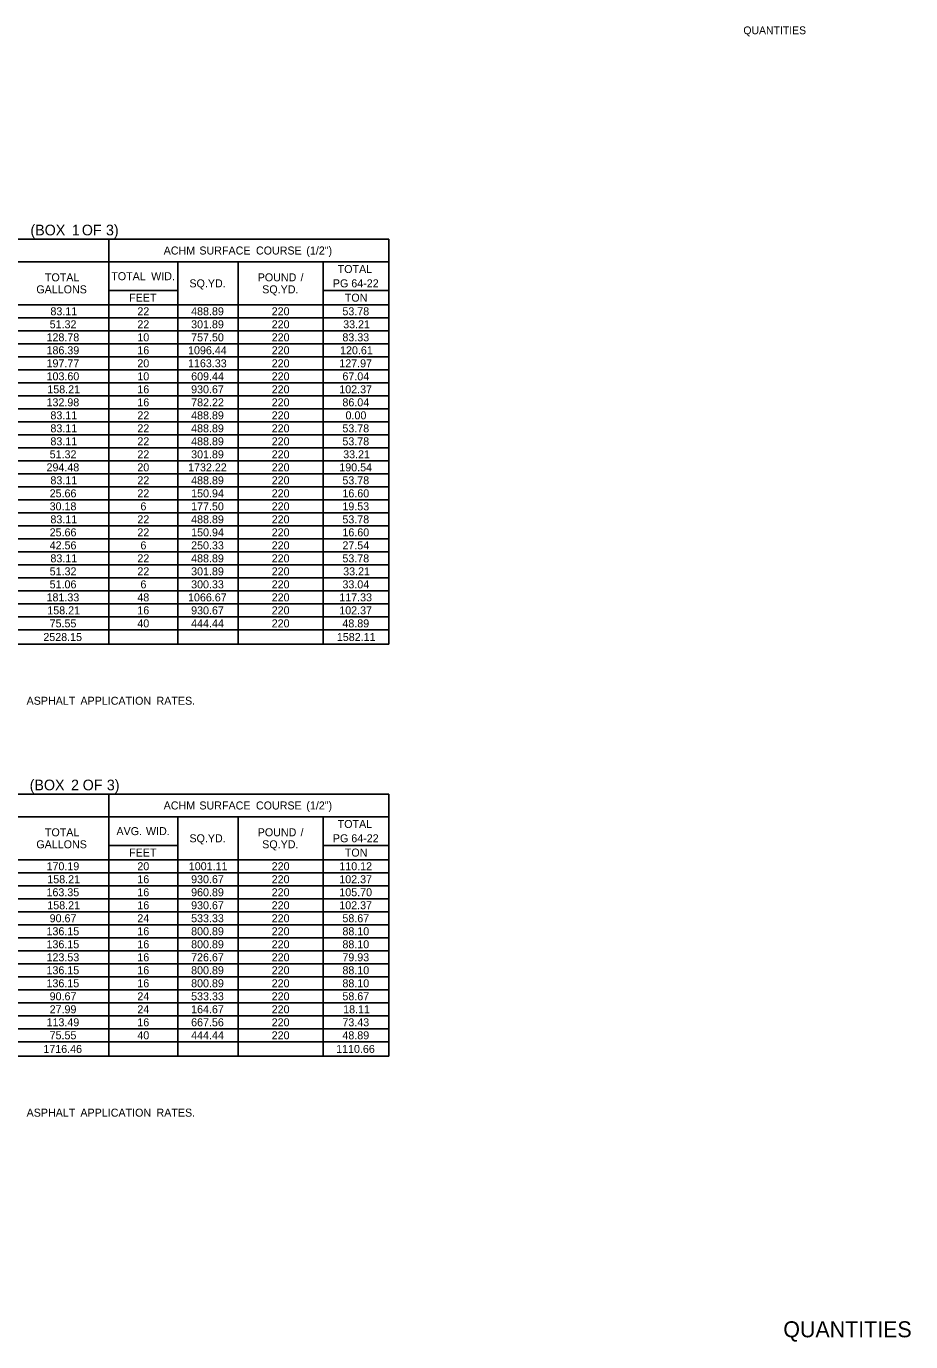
# Model space of a CAD drawing. Extents: x 544250 to 1930787, y -1948365 to 596640.
# Drawn here: x 552725 to 553389, y -1947044 to -1946058 of the extents above; entities that cross this region are included whole.
import ezdxf

# ---------------------------------------------------------------- set-up
doc = ezdxf.new("R2010")
doc.units = 0
for name, color, linetype in [('Default', 7, 'Continuous'), ('R_Border', 7, 'Continuous'), ('R_Border Prem', 7, 'Continuous')]:
    doc.layers.add(name, color=color, linetype=linetype)

msp = doc.modelspace()

# ---------------------------------------------------------------- linework, layer by layer
at = {"layer": 'Default'}
for p, q in [((552201.23, -1946217.53), (552997.32, -1946217.53)), ((552787.2, -1946521.24), (552787.2, -1946217.53)), ((552997.32, -1946521.24), (552997.32, -1946217.53)), ((552612.68, -1946234.59), (552997.32, -1946234.59)), ((552838.88, -1946234.59), (552884.22, -1946234.59)), ((552838.88, -1946521.24), (552838.88, -1946234.59)), ((552884.22, -1946521.24), (552884.22, -1946234.59)), ((552948.08, -1946521.24), (552948.08, -1946234.59)), ((552787.2, -1946256.04), (552838.88, -1946256.04)), ((552787.2, -1946266.77), (552787.2, -1946256.04)), ((552838.88, -1946266.77), (552838.88, -1946256.04)), ((552948.08, -1946256.04), (552997.32, -1946256.04)), ((552413.78, -1946266.77), (552997.32, -1946266.77)), ((552672.15, -1946266.77), (552838.88, -1946266.77)), ((552838.88, -1946266.77), (552997.32, -1946266.77)), ((552413.78, -1946276.52), (552997.32, -1946276.52)), ((552201.23, -1946286.27), (552997.32, -1946286.27)), ((552201.23, -1946286.27), (552997.32, -1946286.27)), ((552201.23, -1946296.02), (552997.32, -1946296.02)), ((552201.23, -1946296.02), (552997.32, -1946296.02)), ((552201.23, -1946305.77), (552997.32, -1946305.77)), ((552201.23, -1946305.77), (552997.32, -1946305.77)), ((552201.23, -1946315.52), (552997.32, -1946315.52)), ((552201.23, -1946315.52), (552997.32, -1946315.52)), ((552201.23, -1946325.27), (552997.32, -1946325.27)), ((552201.23, -1946325.27), (552997.32, -1946325.27)), ((552201.23, -1946335.02), (552997.32, -1946335.02)), ((552201.23, -1946335.02), (552997.32, -1946335.02)), ((552201.23, -1946344.77), (552997.32, -1946344.77)), ((552201.23, -1946344.77), (552997.32, -1946344.77)), ((552201.23, -1946354.52), (552997.32, -1946354.52)), ((552201.23, -1946364.27), (552997.32, -1946364.27)), ((552672.15, -1946364.27), (552997.32, -1946364.27)), ((552672.15, -1946374.02), (552997.32, -1946374.02)), ((552201.23, -1946383.77), (552997.32, -1946383.77)), ((552201.23, -1946383.77), (552997.32, -1946383.77)), ((552201.23, -1946393.52), (552997.32, -1946393.52)), ((552201.23, -1946393.52), (552997.32, -1946393.52)), ((552413.78, -1946403.27), (552997.32, -1946403.27)), ((552413.78, -1946413.02), (552997.32, -1946413.02)), ((552201.23, -1946422.77), (552997.32, -1946422.77)), ((552201.23, -1946422.77), (552997.32, -1946422.77)), ((552413.78, -1946432.52), (552997.32, -1946432.52)), ((552413.78, -1946442.27), (552997.32, -1946442.27)), ((552201.23, -1946452.02), (552997.32, -1946452.02)), ((552201.23, -1946452.02), (552997.32, -1946452.02)), ((552413.78, -1946461.77), (552997.32, -1946461.77)), ((552413.78, -1946471.52), (552997.32, -1946471.52)), ((552201.23, -1946481.27), (552997.32, -1946481.27)), ((552413.78, -1946491.02), (552997.32, -1946491.02)), ((552672.15, -1946491.02), (552997.32, -1946491.02)), ((552201.23, -1946500.77), (552997.32, -1946500.77)), ((552413.78, -1946500.77), (552997.32, -1946500.77)), ((552201.23, -1946510.52), (552997.32, -1946510.52)), ((552201.23, -1946521.24), (552997.32, -1946521.24)), ((552201.23, -1946633.64), (552997.32, -1946633.64)), ((552787.2, -1946830.1), (552787.2, -1946633.64)), ((552997.32, -1946830.1), (552997.32, -1946633.64)), ((552612.68, -1946650.7), (552997.32, -1946650.7)), ((552838.88, -1946650.7), (552884.22, -1946650.7)), ((552838.88, -1946830.1), (552838.88, -1946650.7)), ((552884.22, -1946830.1), (552884.22, -1946650.7)), ((552948.08, -1946830.1), (552948.08, -1946650.7)), ((552787.2, -1946672.15), (552838.88, -1946672.15)), ((552787.2, -1946682.87), (552787.2, -1946672.15)), ((552838.88, -1946682.87), (552838.88, -1946672.15)), ((552948.08, -1946672.15), (552997.32, -1946672.15)), ((552672.15, -1946682.87), (552838.88, -1946682.87)), ((552838.88, -1946682.87), (552997.32, -1946682.87)), ((552838.88, -1946682.87), (552884.22, -1946682.87)), ((552201.23, -1946692.62), (552997.32, -1946692.62)), ((552201.23, -1946692.62), (552997.32, -1946692.62)), ((552201.23, -1946702.37), (552997.32, -1946702.37)), ((552201.23, -1946702.37), (552997.32, -1946702.37)), ((552201.23, -1946712.12), (552997.32, -1946712.12)), ((552201.23, -1946712.12), (552997.32, -1946712.12)), ((552201.23, -1946721.87), (552997.32, -1946721.87)), ((552413.78, -1946721.87), (552997.32, -1946721.87)), ((552413.78, -1946731.62), (552997.32, -1946731.62)), ((552413.78, -1946731.62), (552997.32, -1946731.62)), ((552201.23, -1946741.37), (552997.32, -1946741.37)), ((552201.23, -1946741.37), (552997.32, -1946741.37)), ((552201.23, -1946751.12), (552997.32, -1946751.12)), ((552201.23, -1946751.12), (552997.32, -1946751.12)), ((552201.23, -1946760.87), (552997.32, -1946760.87)), ((552201.23, -1946760.87), (552997.32, -1946760.87)), ((552201.23, -1946770.62), (552997.32, -1946770.62)), ((552201.23, -1946770.62), (552997.32, -1946770.62)), ((552201.23, -1946780.37), (552997.32, -1946780.37)), ((552413.78, -1946780.37), (552997.32, -1946780.37)), ((552413.78, -1946790.12), (552997.32, -1946790.12)), ((552413.78, -1946799.87), (552997.32, -1946799.87)), ((552672.15, -1946799.87), (552997.32, -1946799.87)), ((552201.23, -1946809.62), (552997.32, -1946809.62)), ((552413.78, -1946809.62), (552997.32, -1946809.62)), ((552201.23, -1946819.37), (552997.32, -1946819.37)), ((552201.23, -1946830.1), (552997.32, -1946830.1))]:
    msp.add_line(p, q, dxfattribs=at)

# ---------------------------------------------------------------- texts
for s, height, p in [(' (BOX', 8, (552725.4, -1946214.7)), (' 1', 8, (552756.44, -1946214.7)), (' OF', 8, (552763.95, -1946214.7)), (' 3)', 8, (552782.06, -1946214.7)), ('ACHM', 6, (552828.33, -1946229.06)), (' SURFACE', 6, (552852.88, -1946229.06)), (' COURSE', 6, (552895.32, -1946229.06)), (' (1/2")', 6, (552933.1, -1946229.06)), ('TOTAL', 6, (552739.23, -1946249.18)), ('TOTAL', 6, (552789.01, -1946248.32)), (' WID.', 6, (552816.7, -1946248.32)), ('POUND', 6, (552898.88, -1946249.18)), (' /', 6, (552928.75, -1946249.18)), ('TOTAL', 6, (552958.85, -1946242.95)), ('GALLONS', 6, (552732.79, -1946258.18)), ('SQ.YD.', 6, (552847.63, -1946253.68)), ('SQ.YD.', 6, (552902.23, -1946258.18)), ('PG', 6, (552955.23, -1946253.68)), (' 64-22', 6, (552966.83, -1946253.68)), ('FEET', 6, (552802.41, -1946264.4)), ('TON', 6, (552964.19, -1946264.4)), ('83.11', 6, (552743.37, -1946274.64)), ('22', 6, (552808.6, -1946274.64)), ('488.89', 6, (552848.92, -1946274.64)), ('220', 6, (552909.36, -1946274.64)), ('53.78', 6, (552962.4, -1946274.64)), ('51.32', 6, (552742.82, -1946284.39)), ('22', 6, (552808.6, -1946284.39)), ('301.89', 6, (552848.92, -1946284.39)), ('220', 6, (552909.36, -1946284.39)), ('33.21', 6, (552962.98, -1946284.39)), ('128.78', 6, (552740.45, -1946294.14)), ('10', 6, (552808.58, -1946294.14)), ('757.50', 6, (552848.94, -1946294.14)), ('220', 6, (552909.36, -1946294.14)), ('83.33', 6, (552962.4, -1946294.14)), ('186.39', 6, (552740.45, -1946303.89)), ('16', 6, (552808.57, -1946303.89)), ('1096.44', 6, (552846.61, -1946303.89)), ('220', 6, (552909.36, -1946303.89)), ('120.61', 6, (552960.65, -1946303.89)), ('197.77', 6, (552740.46, -1946313.64)), ('20', 6, (552808.58, -1946313.64)), ('1163.33', 6, (552846.59, -1946313.64)), ('220', 6, (552909.36, -1946313.64)), ('127.97', 6, (552960.07, -1946313.64)), ('103.60', 6, (552740.47, -1946323.39)), ('10', 6, (552808.58, -1946323.39)), ('609.44', 6, (552848.94, -1946323.39)), ('220', 6, (552909.36, -1946323.39)), ('67.04', 6, (552962.42, -1946323.39)), ('158.21', 6, (552741.04, -1946333.14)), ('16', 6, (552808.57, -1946333.14)), ('930.67', 6, (552848.92, -1946333.14)), ('220', 6, (552909.36, -1946333.14)), ('102.37', 6, (552960.07, -1946333.14)), ('132.98', 6, (552740.45, -1946342.89)), ('16', 6, (552808.57, -1946342.89)), ('782.22', 6, (552848.96, -1946342.89)), ('220', 6, (552909.36, -1946342.89)), ('86.04', 6, (552962.42, -1946342.89)), ('83.11', 6, (552743.37, -1946352.64)), ('22', 6, (552808.6, -1946352.64)), ('488.89', 6, (552848.92, -1946352.64)), ('220', 6, (552909.36, -1946352.64)), ('0.00', 6, (552964.75, -1946352.64)), ('83.11', 6, (552743.37, -1946362.39)), ('22', 6, (552808.6, -1946362.39)), ('488.89', 6, (552848.92, -1946362.39)), ('220', 6, (552909.36, -1946362.39)), ('53.78', 6, (552962.4, -1946362.39)), ('83.11', 6, (552743.37, -1946372.14)), ('22', 6, (552808.6, -1946372.14)), ('488.89', 6, (552848.92, -1946372.14)), ('220', 6, (552909.36, -1946372.14)), ('53.78', 6, (552962.4, -1946372.14)), ('51.32', 6, (552742.82, -1946381.89)), ('22', 6, (552808.6, -1946381.89)), ('301.89', 6, (552848.92, -1946381.89)), ('220', 6, (552909.36, -1946381.89)), ('33.21', 6, (552962.98, -1946381.89)), ('294.48', 6, (552740.45, -1946391.64)), ('20', 6, (552808.58, -1946391.64)), ('1732.22', 6, (552846.63, -1946391.64)), ('220', 6, (552909.36, -1946391.64)), ('190.54', 6, (552960.09, -1946391.64)), ('83.11', 6, (552743.37, -1946401.39)), ('22', 6, (552808.6, -1946401.39)), ('488.89', 6, (552848.92, -1946401.39)), ('220', 6, (552909.36, -1946401.39)), ('53.78', 6, (552962.4, -1946401.39)), ('25.66', 6, (552742.79, -1946411.14)), ('22', 6, (552808.6, -1946411.14)), ('150.94', 6, (552848.94, -1946411.14)), ('220', 6, (552909.36, -1946411.14)), ('16.60', 6, (552962.42, -1946411.14)), ('30.18', 6, (552742.78, -1946420.89)), ('6', 6, (552810.9, -1946420.89)), ('177.50', 6, (552848.94, -1946420.89)), ('220', 6, (552909.36, -1946420.89)), ('19.53', 6, (552962.4, -1946420.89)), ('83.11', 6, (552743.37, -1946430.64)), ('22', 6, (552808.6, -1946430.64)), ('488.89', 6, (552848.92, -1946430.64)), ('220', 6, (552909.36, -1946430.64)), ('53.78', 6, (552962.4, -1946430.64)), ('25.66', 6, (552742.79, -1946440.39)), ('22', 6, (552808.6, -1946440.39)), ('150.94', 6, (552848.94, -1946440.39)), ('220', 6, (552909.36, -1946440.39)), ('16.60', 6, (552962.42, -1946440.39)), ('42.56', 6, (552742.79, -1946450.14)), ('6', 6, (552810.9, -1946450.14)), ('250.33', 6, (552848.92, -1946450.14)), ('220', 6, (552909.36, -1946450.14)), ('27.54', 6, (552962.42, -1946450.14)), ('83.11', 6, (552743.37, -1946459.89)), ('22', 6, (552808.6, -1946459.89)), ('488.89', 6, (552848.92, -1946459.89)), ('220', 6, (552909.36, -1946459.89)), ('53.78', 6, (552962.4, -1946459.89)), ('51.32', 6, (552742.82, -1946469.64)), ('22', 6, (552808.6, -1946469.64)), ('301.89', 6, (552848.92, -1946469.64)), ('220', 6, (552909.36, -1946469.64)), ('33.21', 6, (552962.98, -1946469.64)), ('51.06', 6, (552742.79, -1946479.39)), ('6', 6, (552810.9, -1946479.39)), ('300.33', 6, (552848.92, -1946479.39)), ('220', 6, (552909.36, -1946479.39)), ('33.04', 6, (552962.42, -1946479.39)), ('181.33', 6, (552740.46, -1946489.14)), ('48', 6, (552808.57, -1946489.14)), ('1066.67', 6, (552846.59, -1946489.14)), ('220', 6, (552909.36, -1946489.14)), ('117.33', 6, (552960.07, -1946489.14)), ('158.21', 6, (552741.04, -1946498.89)), ('16', 6, (552808.57, -1946498.89)), ('930.67', 6, (552848.92, -1946498.89)), ('220', 6, (552909.36, -1946498.89)), ('102.37', 6, (552960.07, -1946498.89)), ('75.55', 6, (552742.76, -1946508.64)), ('40', 6, (552808.58, -1946508.64)), ('444.44', 6, (552848.94, -1946508.64)), ('220', 6, (552909.36, -1946508.64)), ('48.89', 6, (552962.4, -1946508.64)), ('2528.15', 6, (552738.06, -1946518.88)), ('1582.11', 6, (552958.23, -1946518.88)), (' ASPHALT', 6, (552723.26, -1946566.65)), (' APPLICATION', 6, (552763.63, -1946566.65)), (' RATES.', 6, (552820.71, -1946566.65)), (' (BOX', 8, (552724.82, -1946630.81)), (' 2', 8, (552755.86, -1946630.81)), (' OF', 8, (552764.61, -1946630.81)), (' 3)', 8, (552782.72, -1946630.81)), ('ACHM', 6, (552828.33, -1946645.17)), (' SURFACE', 6, (552852.88, -1946645.17)), (' COURSE', 6, (552895.32, -1946645.17)), (' (1/2")', 6, (552933.1, -1946645.17)), ('AVG.', 6, (552792.9, -1946664.42)), (' WID.', 6, (552812.82, -1946664.42)), (' /', 6, (552928.75, -1946665.29)), ('TOTAL', 6, (552958.85, -1946659.06)), ('GALLONS', 6, (552732.79, -1946674.29)), ('TOTAL', 6, (552739.23, -1946665.29)), ('SQ.YD.', 6, (552847.63, -1946669.79)), ('POUND', 6, (552898.88, -1946665.29)), ('SQ.YD.', 6, (552902.23, -1946674.29)), ('PG', 6, (552955.23, -1946669.79)), (' 64-22', 6, (552966.83, -1946669.79)), ('FEET', 6, (552802.41, -1946680.51)), ('TON', 6, (552964.19, -1946680.51)), ('170.19', 6, (552740.45, -1946690.75)), ('20', 6, (552808.58, -1946690.75)), ('1001.11', 6, (552847.17, -1946690.75)), ('220', 6, (552909.36, -1946690.75)), ('110.12', 6, (552960.11, -1946690.75)), ('158.21', 6, (552741.04, -1946700.5)), ('16', 6, (552808.57, -1946700.5)), ('930.67', 6, (552848.92, -1946700.5)), ('220', 6, (552909.36, -1946700.5)), ('102.37', 6, (552960.07, -1946700.5)), ('163.35', 6, (552740.43, -1946710.25)), ('16', 6, (552808.57, -1946710.25)), ('960.89', 6, (552848.92, -1946710.25)), ('220', 6, (552909.36, -1946710.25)), ('105.70', 6, (552960.09, -1946710.25)), ('158.21', 6, (552741.04, -1946720)), ('16', 6, (552808.57, -1946720)), ('930.67', 6, (552848.92, -1946720)), ('220', 6, (552909.36, -1946720)), ('102.37', 6, (552960.07, -1946720)), ('90.67', 6, (552742.79, -1946729.75)), ('24', 6, (552808.59, -1946729.75)), ('533.33', 6, (552848.92, -1946729.75)), ('220', 6, (552909.36, -1946729.75)), ('58.67', 6, (552962.4, -1946729.75)), ('136.15', 6, (552740.43, -1946739.5)), ('16', 6, (552808.57, -1946739.5)), ('800.89', 6, (552848.92, -1946739.5)), ('220', 6, (552909.36, -1946739.5)), ('88.10', 6, (552962.42, -1946739.5)), ('136.15', 6, (552740.43, -1946749.25)), ('16', 6, (552808.57, -1946749.25)), ('800.89', 6, (552848.92, -1946749.25)), ('220', 6, (552909.36, -1946749.25)), ('88.10', 6, (552962.42, -1946749.25)), ('123.53', 6, (552740.46, -1946759)), ('16', 6, (552808.57, -1946759)), ('726.67', 6, (552848.92, -1946759)), ('220', 6, (552909.36, -1946759)), ('79.93', 6, (552962.4, -1946759)), ('136.15', 6, (552740.43, -1946768.75)), ('16', 6, (552808.57, -1946768.75)), ('800.89', 6, (552848.92, -1946768.75)), ('220', 6, (552909.36, -1946768.75)), ('88.10', 6, (552962.42, -1946768.75)), ('136.15', 6, (552740.43, -1946778.5)), ('16', 6, (552808.57, -1946778.5)), ('800.89', 6, (552848.92, -1946778.5)), ('220', 6, (552909.36, -1946778.5)), ('88.10', 6, (552962.42, -1946778.5)), ('90.67', 6, (552742.79, -1946788.25)), ('24', 6, (552808.59, -1946788.25)), ('533.33', 6, (552848.92, -1946788.25)), ('220', 6, (552909.36, -1946788.25)), ('58.67', 6, (552962.4, -1946788.25)), ('27.99', 6, (552742.78, -1946798)), ('24', 6, (552808.59, -1946798)), ('164.67', 6, (552848.92, -1946798)), ('220', 6, (552909.36, -1946798)), ('18.11', 6, (552962.98, -1946798)), ('113.49', 6, (552740.45, -1946807.75)), ('16', 6, (552808.57, -1946807.75)), ('667.56', 6, (552848.92, -1946807.75)), ('220', 6, (552909.36, -1946807.75)), ('73.43', 6, (552962.4, -1946807.75)), ('75.55', 6, (552742.76, -1946817.5)), ('40', 6, (552808.58, -1946817.5)), ('444.44', 6, (552848.94, -1946817.5)), ('220', 6, (552909.36, -1946817.5)), ('48.89', 6, (552962.4, -1946817.5)), ('1716.46', 6, (552738.08, -1946827.74)), ('1110.66', 6, (552957.7, -1946827.74)), (' ASPHALT', 6, (552723.26, -1946875.51)), (' APPLICATION', 6, (552763.63, -1946875.51)), (' RATES.', 6, (552820.71, -1946875.51))]:
    msp.add_text(s, height=height, dxfattribs=at).set_placement(p)
at = {"layer": 'R_Border'}
msp.add_text('QUANTITIES', height=12, rotation=360, dxfattribs=at).set_placement((553293.15, -1947040.95))
at = {"layer": 'R_Border Prem'}
msp.add_text('QUANTITIES', height=5.862, rotation=360, dxfattribs=at).set_placement((553263.17, -1946063.9))

doc.saveas('drawing.dxf')
